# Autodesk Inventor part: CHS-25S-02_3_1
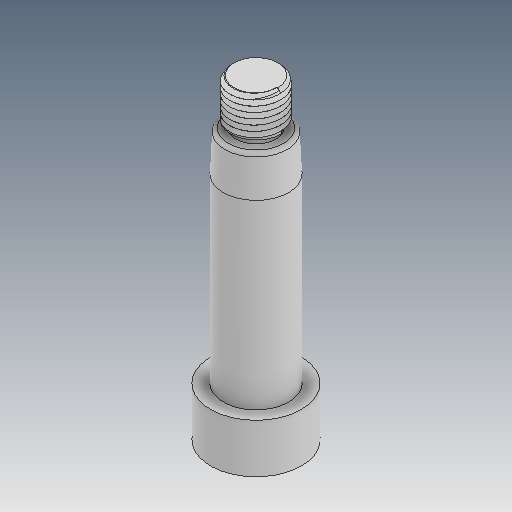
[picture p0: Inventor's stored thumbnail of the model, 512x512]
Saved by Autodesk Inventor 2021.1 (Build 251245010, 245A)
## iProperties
Created: 2019-04
Part Number: CHS-25S-02_3_1
Material: Ogólny
Document SubType Name: Modeling
Designer: user
Density: 1 g/cm^3
Appearance: Domyślna
Author: user
Revision Number: ÈÎºÎ
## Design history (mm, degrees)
feature "ÊäÈë1"
feature "ÊäÈë2"
node "Bryła1"
node "Bryła2"
